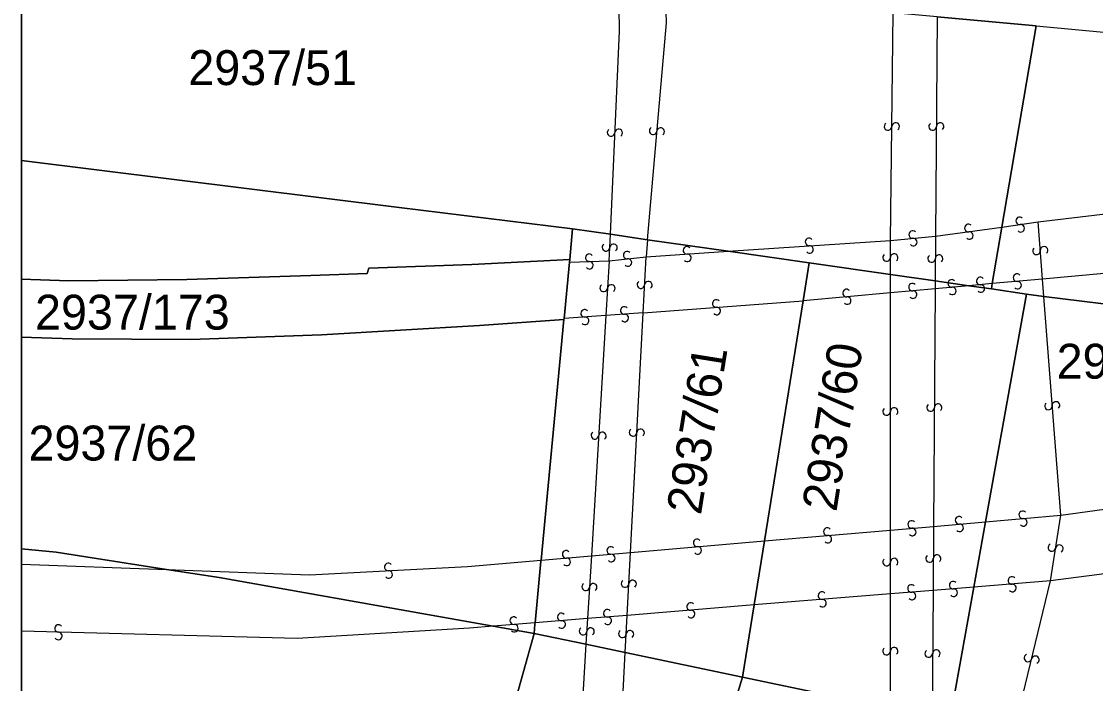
# Model space of a CAD drawing. Extents: x -596024 to -594475, y -1163820 to -1161957.
# Drawn here: x -596024.4 to -595972.1, y -1163222.9 to -1163190.6 of the extents above; entities that cross this region are included whole.
import ezdxf

# ---------------------------------------------------------------- set-up
doc = ezdxf.new("R2010")
doc.units = 0
for name, color, linetype in [('Level 1', 7, 'Continuous'), ('Level 13', 7, 'Continuous'), ('Level 3', 7, 'Continuous'), ('Level 4', 7, 'Continuous'), ('Level 60', 7, 'Continuous'), ('Vrstva 60', 7, 'Continuous'), ('Vrstva 63', 7, 'Continuous')]:
    doc.layers.add(name, color=color, linetype=linetype)

msp = doc.modelspace()

# ---------------------------------------------------------------- linework, layer by layer
at = {"layer": 'Level 1'}
for points in [[(-595979.83, -1163190.41), (-595975, -1163190.85)], [(-595975, -1163190.85), (-595976.67, -1163200.65)], [(-595975, -1163190.85), (-595968.07, -1163191.49), (-595955.73, -1163192.42), (-595936.94, -1163194.36)], [(-596024.42, -1163197.407), (-596006.03, -1163199.69), (-595997.58, -1163200.74)], [(-595976.67, -1163200.65), (-595977.14, -1163203.41)], [(-595997.58, -1163200.74), (-595997.72, -1163202.23)], [(-595995.74, -1163201), (-595997.58, -1163200.74)], [(-595993.93, -1163201.27), (-595995.74, -1163201)], [(-595990, -1163201.83), (-595993.93, -1163201.27)], [(-596024.42, -1163203.188), (-596022.11, -1163203.27), (-596016.36, -1163203.2), (-596010.33, -1163203.01), (-596007.59, -1163202.92), (-596007.51, -1163202.66), (-596002.49, -1163202.48), (-595997.72, -1163202.23)], [(-595997.72, -1163202.23), (-595997.73, -1163202.36)], [(-595986.05, -1163202.4), (-595990, -1163201.83)], [(-595997.73, -1163202.36), (-595997.99, -1163205.11)], [(-595986.05, -1163202.4), (-595986.35, -1163204.24)], [(-595982.1, -1163202.97), (-595986.05, -1163202.4)], [(-595979.92, -1163203.28), (-595982.1, -1163202.97)], [(-595978.28, -1163203.51), (-595979.92, -1163203.28)], [(-595977.18, -1163203.67), (-595978.28, -1163203.51)], [(-595977.14, -1163203.41), (-595977.18, -1163203.67)], [(-595975.47, -1163203.92), (-595977.18, -1163203.67)], [(-595986.35, -1163204.24), (-595988.23, -1163215.95)], [(-595975.47, -1163203.92), (-595977.47, -1163215.02)], [(-595974.63, -1163204.03), (-595975.47, -1163203.92)], [(-595964.36, -1163205.23), (-595967.35, -1163204.93), (-595974.63, -1163204.03)], [(-595998, -1163205.15), (-596002.11, -1163205.45), (-596009.8, -1163205.91), (-596016.17, -1163206.14), (-596021.95, -1163206.1), (-596024.42, -1163206.016)], [(-595998, -1163205.15), (-595999.11, -1163216.89)], [(-595997.99, -1163205.11), (-595998, -1163205.15)], [(-595977.47, -1163215.02), (-595978.04, -1163218.21)], [(-596024.42, -1163216.329), (-596022.73, -1163216.5), (-596017.35, -1163217.34)], [(-595988.23, -1163215.95), (-595988.73, -1163219.07)], [(-595999.11, -1163216.89), (-595999.12, -1163216.94), (-595999.4, -1163219.94)], [(-596017.35, -1163217.34), (-596014.8, -1163217.74), (-596001.45, -1163220.11)], [(-595978.04, -1163218.21), (-595979.21, -1163224.7)], [(-595988.73, -1163219.07), (-595989.3, -1163222.59)], [(-595999.4, -1163219.94), (-595999.41, -1163220.01), (-595999.45, -1163220.46)], [(-595999.45, -1163220.46), (-596001.59, -1163228.13)], [(-595999.45, -1163220.46), (-596001.45, -1163220.11)], [(-595996.93, -1163220.99), (-595999.45, -1163220.46)], [(-595995.02, -1163221.39), (-595996.93, -1163220.99)], [(-595989.3, -1163222.59), (-595995.02, -1163221.39)], [(-595989.3, -1163222.59), (-595990.04, -1163224.98)], [(-595982.1, -1163224.1), (-595989.3, -1163222.59)]]:
    msp.add_lwpolyline(points, dxfattribs=at)
at = {"layer": 'Level 13'}
for centre, start, end in [((-595995.704, -1163196.04), 124.8279, 356.9259), ((-595995.336, -1163196.059), 304.6135, 177.2035), ((-595993.654, -1163195.962), 122.3445, 354.4425), ((-595993.287, -1163195.997), 302.1301, 174.7201), ((-595982.214, -1163195.746), 126.6495, 358.7475), ((-595981.846, -1163195.753), 306.435, 179.025), ((-595980.044, -1163195.748), 126.7831, 359.3731), ((-595979.676, -1163195.753), 306.9976, 179.0956), ((-595975.804, -1163200.347), 45.4122, 277.5102), ((-595978.304, -1163200.697), 45.3041, 277.4021), ((-595975.755, -1163200.712), 225.1977, 97.7877), ((-595986.061, -1163201.376), 41.2109, 273.3089), ((-595981.015, -1163201.016), 42.5672, 274.6652), ((-595980.984, -1163201.383), 222.3527, 94.9427), ((-595978.255, -1163201.062), 225.0896, 97.6796), ((-595995.954, -1163201.64), 124.7302, 356.8282), ((-595995.586, -1163201.659), 304.5157, 177.1057), ((-595992.011, -1163201.786), 41.2343, 273.3323), ((-595986.038, -1163201.744), 220.9964, 93.5864), ((-595974.984, -1163201.812), 131.6772, 3.7752), ((-595974.616, -1163201.787), 311.4627, 184.0527), ((-595996.764, -1163202.146), 39.1534, 271.2514), ((-595994.919, -1163202.017), 43.7129, 275.8109), ((-595994.88, -1163202.383), 223.4985, 96.0885), ((-595991.988, -1163202.154), 221.0199, 93.6099), ((-595982.284, -1163202.138), 127.3727, 359.4707), ((-595981.916, -1163202.141), 307.1583, 179.7483), ((-595980.094, -1163202.188), 126.6326, 359.2226), ((-595979.726, -1163202.193), 306.8471, 178.9451), ((-595996.755, -1163202.514), 218.9389, 91.5289), ((-595994.254, -1163203.459), 124.4371, 356.5351), ((-595993.886, -1163203.48), 304.2226, 176.8126), ((-595979.116, -1163203.397), 42.3842, 274.9742), ((-595977.725, -1163203.277), 42.1714, 274.7614), ((-595975.936, -1163203.117), 42.2894, 274.8794), ((-595975.905, -1163203.484), 222.5039, 94.6019), ((-595996.064, -1163203.618), 123.7161, 356.3061), ((-595995.696, -1163203.643), 303.9305, 176.0285), ((-595984.236, -1163203.867), 42.2676, 274.8576), ((-595981.026, -1163203.577), 42.4001, 274.9901), ((-595980.995, -1163203.944), 222.6146, 94.7126), ((-595979.085, -1163203.764), 222.5987, 94.6967), ((-595977.696, -1163203.644), 222.3858, 94.4838), ((-595990.582, -1163204.376), 41.618, 273.716), ((-595984.205, -1163204.234), 222.4821, 94.5801), ((-595996.993, -1163204.856), 41.3843, 273.9743), ((-595995.062, -1163204.716), 41.2439, 273.8339), ((-595995.039, -1163205.084), 221.4584, 93.5563), ((-595990.557, -1163204.744), 221.4035, 93.9935), ((-595996.968, -1163205.224), 221.5987, 93.6967), ((-595982.284, -1163209.638), 127.3727, 359.4707), ((-595981.916, -1163209.641), 307.1583, 179.7483), ((-595980.144, -1163209.448), 126.7625, 359.3525), ((-595979.776, -1163209.453), 306.9769, 179.0749), ((-595974.404, -1163209.373), 131.8207, 3.9187), ((-595974.036, -1163209.347), 311.6063, 184.1963), ((-595996.494, -1163210.808), 123.7402, 356.3302), ((-595996.126, -1163210.833), 303.9547, 176.0527), ((-595994.634, -1163210.659), 124.3342, 356.4322), ((-595994.266, -1163210.681), 304.1197, 176.7097), ((-595978.754, -1163214.946), 42.3425, 274.4405), ((-595975.654, -1163214.676), 42.3559, 274.4539), ((-595985.174, -1163215.496), 42.3142, 274.4122), ((-595981.064, -1163215.146), 42.2718, 274.3698), ((-595981.035, -1163215.513), 222.0574, 94.6474), ((-595978.725, -1163215.313), 222.128, 94.718), ((-595975.625, -1163215.043), 222.1415, 94.7315), ((-595991.514, -1163216.046), 42.2743, 274.3723), ((-595985.145, -1163215.863), 222.0998, 94.6898), ((-595997.894, -1163216.606), 42.2718, 274.3698), ((-595995.725, -1163216.416), 42.4856, 274.5836), ((-595991.485, -1163216.413), 222.0599, 94.6499), ((-595974.232, -1163216.27), 118.4921, 350.5901), ((-595973.868, -1163216.329), 298.2776, 170.8676), ((-595997.865, -1163216.973), 222.0574, 94.6474), ((-595995.694, -1163216.783), 222.2711, 94.8611), ((-595982.284, -1163216.978), 127.3727, 359.4707), ((-595981.916, -1163216.981), 307.1583, 179.7483), ((-595980.194, -1163216.808), 126.7922, 359.3822), ((-595979.826, -1163216.813), 307.0066, 179.1046), ((-596006.558, -1163217.216), 40.3465, 272.4445), ((-596006.541, -1163217.584), 220.132, 92.722), ((-595995.024, -1163218.029), 124.3893, 356.4873), ((-595994.656, -1163218.05), 304.1749, 176.7649), ((-595979.044, -1163218.106), 41.7782, 274.3682), ((-595976.184, -1163217.877), 41.8966, 274.4866), ((-595996.944, -1163218.188), 123.5936, 356.1836), ((-595996.576, -1163218.213), 303.8081, 175.9061), ((-595985.434, -1163218.616), 41.8146, 274.4046), ((-595981.073, -1163218.266), 41.557, 274.147), ((-595981.048, -1163218.634), 221.7714, 93.8694), ((-595979.017, -1163218.474), 221.9927, 94.0907), ((-595976.156, -1163218.244), 222.111, 94.209), ((-595991.834, -1163219.146), 41.8683, 274.4583), ((-595985.407, -1163218.984), 222.0291, 94.1271), ((-595998.134, -1163219.656), 41.8661, 274.4561), ((-595995.893, -1163219.476), 41.6024, 274.1924), ((-595991.807, -1163219.514), 222.0828, 94.1807), ((-596022.614, -1163220.216), 35.6541, 268.2441), ((-596000.444, -1163219.837), 41.8988, 274.4888), ((-596000.416, -1163220.204), 222.1132, 94.2112), ((-595998.107, -1163220.024), 222.0806, 94.1786), ((-595995.867, -1163219.844), 221.8168, 93.9148), ((-596022.627, -1163220.584), 215.8685, 87.9665), ((-595997.074, -1163220.348), 123.5253, 356.1153), ((-595996.706, -1163220.373), 303.7398, 175.8378), ((-595995.154, -1163220.478), 124.2104, 356.3084), ((-595994.786, -1163220.501), 303.996, 176.586), ((-595982.284, -1163221.318), 127.3727, 359.4707), ((-595981.916, -1163221.321), 307.1583, 179.7483), ((-595980.234, -1163221.438), 126.6925, 359.2825), ((-595979.866, -1163221.443), 306.9069, 179.0049), ((-595975.399, -1163221.655), 113.8171, 345.9151), ((-595975.041, -1163221.744), 293.6026, 166.1926)]:
    msp.add_arc(centre, 0.184, start, end, dxfattribs=at)
at = {"layer": 'Level 3'}
msp.add_line((-596024.42, -1163217.077), (-596017.35, -1163217.34), dxfattribs=at)
for points in [[(-595995.74, -1163201), (-595995.3, -1163191.1), (-595995.33, -1163188.77)], [(-595993.93, -1163201.27), (-595993, -1163190.7), (-595993.06, -1163189.03)], [(-595982.1, -1163201.3), (-595981.96, -1163190.21)], [(-595979.83, -1163190.41), (-595979.9, -1163201.1)], [(-595974.9, -1163200.4), (-595967.4, -1163199.5)], [(-595979.9, -1163201.1), (-595976.67, -1163200.65)], [(-595976.67, -1163200.65), (-595974.9, -1163200.4)], [(-595974.69, -1163203.19), (-595974.9, -1163200.4)], [(-595995.8, -1163202.3), (-595995.74, -1163201)], [(-595982.1, -1163201.3), (-595979.9, -1163201.1)], [(-595979.9, -1163201.1), (-595979.92, -1163203.28)], [(-595993.93, -1163201.27), (-595994, -1163202.1)], [(-595990, -1163201.83), (-595982.1, -1163201.3)], [(-595982.1, -1163202.97), (-595982.1, -1163201.3)], [(-595997.73, -1163202.36), (-595995.8, -1163202.3)], [(-595995.8, -1163202.3), (-595995.96, -1163204.96)], [(-595995.8, -1163202.3), (-595994, -1163202.1)], [(-595994.14, -1163204.83), (-595994, -1163202.1)], [(-595994, -1163202.1), (-595990, -1163201.83)], [(-595967.1, -1163202.5), (-595974.69, -1163203.19)], [(-595982.1, -1163203.86), (-595982.1, -1163202.97)], [(-595979.92, -1163203.28), (-595979.92, -1163203.66)], [(-595974.69, -1163203.19), (-595977.14, -1163203.41)], [(-595974.63, -1163204.03), (-595974.69, -1163203.19)], [(-595982.1, -1163203.86), (-595986.35, -1163204.24)], [(-595979.92, -1163203.66), (-595982.1, -1163203.86)], [(-595982.1, -1163215.42), (-595982.1, -1163203.86)], [(-595979.92, -1163203.66), (-595980, -1163215.24)], [(-595978.28, -1163203.51), (-595979.92, -1163203.66)], [(-595977.14, -1163203.41), (-595978.28, -1163203.51)], [(-595994.14, -1163204.83), (-595987, -1163204.3), (-595986.35, -1163204.24)], [(-595973.8, -1163214.7), (-595974.63, -1163204.03)], [(-595994.14, -1163204.83), (-595995.96, -1163204.96)], [(-595994.76, -1163216.51), (-595994.14, -1163204.83)], [(-595995.96, -1163204.96), (-595997.99, -1163205.11)], [(-595995.96, -1163204.96), (-595996.66, -1163216.68)], [(-595973.8, -1163214.7), (-595966.01, -1163213.62)], [(-595977.47, -1163215.02), (-595973.8, -1163214.7)], [(-595974.3, -1163217.9), (-595973.8, -1163214.7)], [(-595982.1, -1163215.42), (-595980, -1163215.24)], [(-595980, -1163215.24), (-595980.02, -1163218.37)], [(-595980, -1163215.24), (-595977.47, -1163215.02)], [(-595988.23, -1163215.95), (-595982.1, -1163215.42)], [(-595982.1, -1163218.53), (-595982.1, -1163215.42)], [(-595994.76, -1163216.51), (-595988.23, -1163215.95)], [(-596017.35, -1163217.34), (-596010.4, -1163217.6), (-596002.7, -1163217.2), (-595999.11, -1163216.89)], [(-595999.11, -1163216.89), (-595996.66, -1163216.68)], [(-595996.66, -1163216.68), (-595996.85, -1163219.73)], [(-595996.66, -1163216.68), (-595994.76, -1163216.51)], [(-595994.92, -1163219.58), (-595994.76, -1163216.51)], [(-595966.66, -1163216.91), (-595974.3, -1163217.9)], [(-595974.3, -1163217.9), (-595978.04, -1163218.21)], [(-595976.13, -1163225.49), (-595974.3, -1163217.9)], [(-595980.02, -1163218.37), (-595982.1, -1163218.53)], [(-595980.02, -1163218.37), (-595980.07, -1163224.52)], [(-595978.04, -1163218.21), (-595980.02, -1163218.37)], [(-595982.1, -1163218.53), (-595988.73, -1163219.07)], [(-595982.1, -1163224.1), (-595982.1, -1163218.53)], [(-595988.73, -1163219.07), (-595994.92, -1163219.58)], [(-595999.4, -1163219.94), (-596001.45, -1163220.11)], [(-595996.85, -1163219.73), (-595999.4, -1163219.94)], [(-595996.85, -1163219.73), (-595996.93, -1163220.99)], [(-595994.92, -1163219.58), (-595996.85, -1163219.73)], [(-595995.02, -1163221.39), (-595994.92, -1163219.58)], [(-596001.45, -1163220.11), (-596002.6, -1163220.2), (-596011, -1163220.7), (-596024.42, -1163220.348)], [(-595996.93, -1163220.99), (-595997.34, -1163227.87)], [(-595995.35, -1163227.75), (-595995.02, -1163221.39)]]:
    msp.add_lwpolyline(points, dxfattribs=at)
at = {"layer": 'Level 60'}
for points in [[(-595975, -1163190.85), (-595968.07, -1163191.49), (-595955.73, -1163192.42), (-595936.94, -1163194.36), (-595930.11, -1163194.78), (-595930.32, -1163197.39), (-595931.1, -1163206.98), (-595931.23, -1163208.58), (-595936.07, -1163208.09), (-595964.36, -1163205.23), (-595967.35, -1163204.93), (-595974.63, -1163204.03), (-595975.47, -1163203.92), (-595977.18, -1163203.67), (-595977.14, -1163203.41), (-595976.67, -1163200.65)], [(-595988.73, -1163219.07), (-595989.3, -1163222.59), (-595995.02, -1163221.39), (-595996.93, -1163220.99), (-595999.45, -1163220.46), (-595999.41, -1163220.01), (-595999.4, -1163219.94), (-595999.12, -1163216.94), (-595999.11, -1163216.89), (-595998, -1163205.15), (-595997.99, -1163205.11), (-595997.73, -1163202.36), (-595997.72, -1163202.23), (-595997.58, -1163200.74), (-595995.74, -1163201), (-595993.93, -1163201.27), (-595990, -1163201.83), (-595986.05, -1163202.4), (-595986.35, -1163204.24), (-595988.23, -1163215.95)], [(-595977.18, -1163203.67), (-595975.47, -1163203.92), (-595977.47, -1163215.02), (-595978.04, -1163218.21), (-595979.21, -1163224.7), (-595980.07, -1163224.52), (-595982.1, -1163224.1), (-595989.3, -1163222.59), (-595988.73, -1163219.07), (-595988.23, -1163215.95), (-595986.35, -1163204.24), (-595986.05, -1163202.4), (-595982.1, -1163202.97), (-595979.92, -1163203.28), (-595978.28, -1163203.51)], [(-595967.35, -1163204.93), (-595964.36, -1163205.23), (-595966.01, -1163213.62), (-595966.66, -1163216.91), (-595968.24, -1163224.95), (-595968.72, -1163227.41), (-595969.83, -1163227.12), (-595975.07, -1163225.77), (-595976.13, -1163225.49), (-595979.21, -1163224.7), (-595978.04, -1163218.21), (-595977.47, -1163215.02), (-595975.47, -1163203.92), (-595974.63, -1163204.03)], [(-595996.9, -1163239.2), (-595995.5, -1163230.5), (-595997.5, -1163230.6), (-595999.76, -1163242.36), (-596005.03, -1163240.49), (-596002.35, -1163230.88), (-596001.59, -1163228.13), (-595999.45, -1163220.46), (-595996.93, -1163220.99), (-595995.02, -1163221.39), (-595989.3, -1163222.59), (-595990.04, -1163224.98), (-595990.82, -1163227.47), (-595991.67, -1163230.19), (-595995.92, -1163243.73), (-595997.81, -1163243.06)], [(-595986.71, -1163226.22), (-595990.04, -1163224.98), (-595989.3, -1163222.59), (-595982.1, -1163224.1), (-595980.07, -1163224.52), (-595979.21, -1163224.7), (-595979.73, -1163226.29), (-595980.09, -1163227.38), (-595980.7, -1163229.26), (-595981.57, -1163231.96), (-595982.13, -1163233.66), (-595988.4, -1163231.54), (-595987.87, -1163229.88), (-595986.99, -1163227.1)]]:
    msp.add_lwpolyline(points, close=True, dxfattribs=at)
at = {"layer": 'Vrstva 60'}
for points in [[(-596024.42, -1163184.047), (-596024.42, -1163197.407), (-596006.03, -1163199.69), (-595997.58, -1163200.74), (-595995.74, -1163201), (-595993.93, -1163201.27), (-595990, -1163201.83), (-595982.1, -1163202.97), (-595979.92, -1163203.28), (-595978.28, -1163203.51), (-595977.18, -1163203.67), (-595977.14, -1163203.41), (-595976.67, -1163200.65), (-595975, -1163190.85), (-595979.83, -1163190.41), (-595981.96, -1163190.21), (-595985.4, -1163189.9), (-595993.06, -1163189.03), (-595995.33, -1163188.77), (-596007.39, -1163187.4), (-596007.44, -1163187.64), (-596022.76, -1163184.39)], [(-596024.42, -1163197.407), (-596024.42, -1163203.188), (-596022.11, -1163203.27), (-596016.36, -1163203.2), (-596010.33, -1163203.01), (-596007.59, -1163202.92), (-596007.51, -1163202.66), (-596002.49, -1163202.48), (-595997.72, -1163202.23), (-595997.58, -1163200.74), (-596006.03, -1163199.69)], [(-596024.42, -1163203.188), (-596024.42, -1163206.016), (-596021.95, -1163206.1), (-596016.17, -1163206.14), (-596009.8, -1163205.91), (-596002.11, -1163205.45), (-595998, -1163205.15), (-595997.99, -1163205.11), (-595997.73, -1163202.36), (-595997.72, -1163202.23), (-596002.49, -1163202.48), (-596007.51, -1163202.66), (-596007.59, -1163202.92), (-596010.33, -1163203.01), (-596016.36, -1163203.2), (-596022.11, -1163203.27)], [(-596024.42, -1163206.016), (-596024.42, -1163216.329), (-596022.73, -1163216.5), (-596017.35, -1163217.34), (-596014.8, -1163217.74), (-596001.45, -1163220.11), (-595999.45, -1163220.46), (-595999.41, -1163220.01), (-595999.4, -1163219.94), (-595999.12, -1163216.94), (-595999.11, -1163216.89), (-595998, -1163205.15), (-596002.11, -1163205.45), (-596009.8, -1163205.91), (-596016.17, -1163206.14), (-596021.95, -1163206.1)], [(-596024.42, -1163216.329), (-596024.42, -1163237.562), (-596024.24, -1163237.84), (-596019.92, -1163241.88), (-596008.01, -1163246.48), (-596006.81, -1163246.88), (-596005.03, -1163240.49), (-596002.35, -1163230.88), (-596001.59, -1163228.13), (-595999.45, -1163220.46), (-596001.45, -1163220.11), (-596014.8, -1163217.74), (-596017.35, -1163217.34), (-596022.73, -1163216.5)]]:
    msp.add_lwpolyline(points, close=True, dxfattribs=at)
msp.add_lwpolyline([(-595979.83, -1163190.41), (-595975, -1163190.85), (-595968.07, -1163191.49)], dxfattribs=at)
at = {"layer": 'Vrstva 63'}
msp.add_lwpolyline([(-594475.47, -1163820.23), (-596024.42, -1163820.23), (-596024.42, -1161956.88), (-594475.47, -1161956.88)], close=True, dxfattribs=at)

# ---------------------------------------------------------------- texts
at = {"layer": 'Level 4'}
for s, p in [('2937/51', (-596016.296, -1163193.73)), ('2937/173', (-596023.76, -1163205.65)), ('2937/59', (-595974.003, -1163208.04)), ('2937/62', (-596024.077, -1163212.03))]:
    msp.add_text(s, height=1.7, dxfattribs=at).set_placement(p)
for s, p in [('2937/60', (-595984.734, -1163214.57)), ('2937/61', (-595991.331, -1163214.724))]:
    msp.add_text(s, height=1.7, rotation=80.8792, dxfattribs=at).set_placement(p)

doc.saveas('drawing.dxf')
